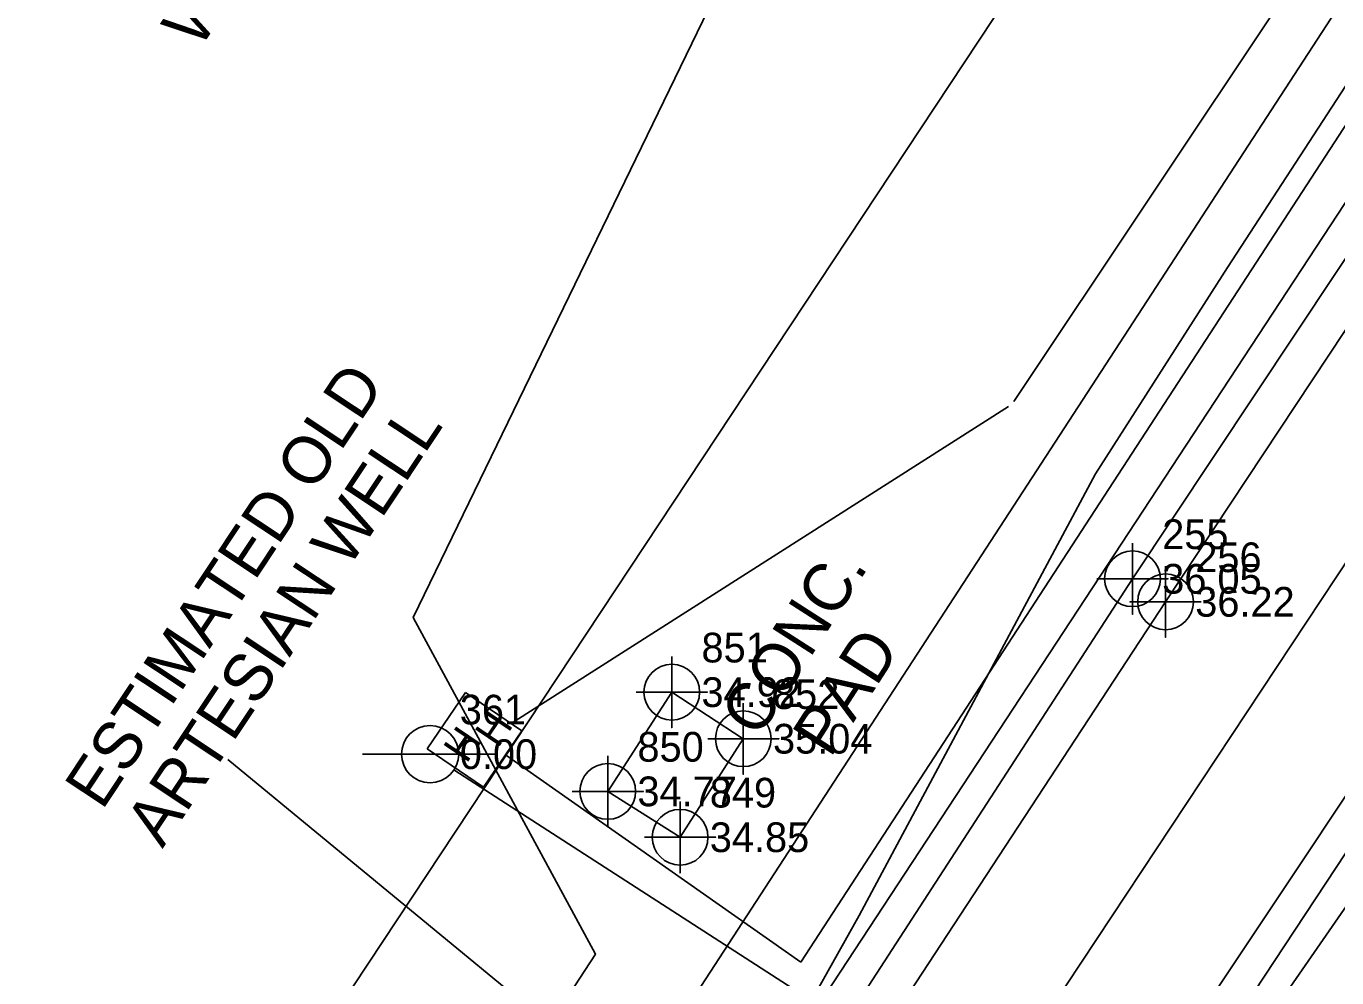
# Model space of a CAD drawing. Extents: x 2603627 to 2605187, y 896619 to 899063.
# Drawn here: x 2604513.4 to 2604623.6, y 898247.7 to 898327.7 of the extents above; entities that cross this region are included whole.
import ezdxf

# ---------------------------------------------------------------- set-up
doc = ezdxf.new("R2010")
doc.units = 0
for name, color, linetype in [('Exist Guardrail', 7, 'Continuous'), ('Exist Horizontal Alignment', 7, 'Continuous'), ('Exist Other Culture Area Outline Leader', 7, 'Continuous'), ('Exist Other Culture Area Outline Text', 7, 'Continuous'), ('Exist Right of Way Line', 7, 'Continuous'), ('Exist Roads EOP', 7, 'Continuous'), ('Exist Roads EOP Cogo Elevation', 7, 'Continuous'), ('Exist Roads EOP Cogo Number', 7, 'Continuous'), ('Exist Roads EOP Cogo Point CELL', 7, 'Continuous'), ('Exist Roads EOP Other', 7, 'Continuous'), ('Exist Roads EOP Other Cogo Elevation', 7, 'Continuous'), ('Exist Roads EOP Other Cogo Number', 7, 'Continuous'), ('Exist Roads EOP Other Cogo Point CELL', 7, 'Continuous'), ('Exist Roads EOP Other Text', 7, 'Continuous'), ('Exist Roads EOT', 7, 'Continuous'), ('Exist Roads EOT Cogo Elevation', 7, 'Continuous'), ('Exist Roads EOT Cogo Number', 7, 'Continuous'), ('Exist Roads EOT Cogo Point CELL', 7, 'Continuous'), ('Exist Utilities Telephone Hand Hole CELL', 7, 'Continuous'), ('Exist Utilities Telephone Pole CELL', 7, 'Continuous'), ('Exist Utilities Telephone Pole Cogo Elevation', 7, 'Continuous'), ('Exist Utilities Telephone Pole Cogo Number', 7, 'Continuous'), ('Exist Utilities Telephone UG Cable SUE LOS C', 7, 'Continuous'), ('Exist Utilities Telephone UG FO SUE LOS C', 7, 'Continuous'), ('Exist Vegetation Woods Line', 7, 'Continuous'), ('Exist Vegetation Woods Line Text', 7, 'Continuous')]:
    doc.layers.add(name, color=color, linetype=linetype)

# ---------------------------------------------------------------- blocks, each defined once
blk = doc.blocks.new('EXIST ROADS EOP COGO POINT')
at = {"layer": 'Exist Roads EOP Cogo Point CELL'}
blk.add_lwpolyline([(0, 0.06), (0, -0.06), (0, 0), (0.06, 0), (-0.06, 0)], dxfattribs=at)
blk.add_circle((0, 0), 0.0469, dxfattribs=at)
blk = doc.blocks.new('EXIST ROADS EOT COGO POINT')
at = {"layer": 'Exist Roads EOT Cogo Point CELL'}
blk.add_lwpolyline([(0, 0.06), (0, -0.06), (0, 0), (-0.06, 0), (0.06, 0)], dxfattribs=at)
blk.add_circle((0, 0), 0.0469, dxfattribs=at)
blk = doc.blocks.new('EXIST ROADS EOP OTHER COGO POINT')
at = {"layer": 'Exist Roads EOP Other Cogo Point CELL'}
blk.add_lwpolyline([(0, 0.06), (0, -0.06), (0, 0), (0.06, 0), (-0.06, 0)], dxfattribs=at)
blk.add_circle((0, 0), 0.0469, dxfattribs=at)

msp = doc.modelspace()

# ---------------------------------------------------------------- linework, layer by layer
at = {"layer": 'Exist Guardrail'}
for points in [[(2604549.45, 898197), (2604551.69, 898200.42), (2604561.03, 898214.38), (2604574.05, 898236.14), (2604583.44, 898252.9), (2604603.34, 898290.06), (2604614.45, 898307.44), (2604661.78, 898380.22)], [(2604631.98, 898264.56), (2604605.99, 898227.06), (2604595.34, 898211.26), (2604574.88, 898180.21)]]:
    msp.add_lwpolyline(points, dxfattribs=at)
at = {"layer": 'Exist Horizontal Alignment'}
msp.add_line((2604537.35, 898151.01), (2604647.76, 898317.92), dxfattribs=at)
at = {"layer": 'Exist Other Culture Area Outline Leader'}
msp.add_line((2604563.19, 898238.98), (2604530.32, 898266.04), dxfattribs=at)
at = {"layer": 'Exist Right of Way Line'}
msp.add_line((2604495.65, 898178.6), (2604606.06, 898345.5), dxfattribs=at)
at = {"layer": 'Exist Roads EOP'}
msp.add_line((2604600.14, 898221.38), (2604629.44, 898265.84), dxfattribs=at)
msp.add_lwpolyline([(2604577.96, 898237.27), (2604606.45, 898281.24), (2604633.89, 898322.5), (2604662.45, 898365.47), (2604690.62, 898408.06), (2604717.29, 898448.09), (2604745.46, 898490.11), (2604773.6, 898532.6), (2604800.88, 898573.95), (2604828.34, 898615.46), (2604855.1, 898656.15), (2604883.53, 898699.09), (2604911.29, 898740.95), (2604939.38, 898783.41), (2604966.33, 898824.04), (2604993.38, 898865.27), (2605022.2, 898908.38), (2605029.46, 898919.46)], dxfattribs=at)
at = {"layer": 'Exist Roads EOP Other'}
msp.add_lwpolyline([(2604568.38, 898259.49), (2604562.29, 898263.35), (2604567.68, 898271.7), (2604573.7, 898267.78), (2604568.38, 898259.49)], dxfattribs=at)
at = {"layer": 'Exist Roads EOT'}
for points in [[(2604580.65, 898235.67), (2604609.23, 898279.3), (2604636.66, 898320.72), (2604665.18, 898363.91), (2604693.37, 898406.36), (2604719.95, 898446.05), (2604748, 898488.34), (2604776.15, 898530.84), (2604803.5, 898572.3), (2604830.95, 898613.91), (2604857.58, 898654.47), (2604886.02, 898697.38), (2604913.86, 898739.33), (2604942.03, 898781.72), (2604969.06, 898822.38), (2604996.07, 898863.44), (2605024.73, 898906.73), (2605032, 898917.78)], [(2604598.04, 898223.4), (2604627.23, 898267.23), (2604654.64, 898308.57), (2604683.28, 898352.01), (2604711.27, 898394.14), (2604737.98, 898434.05), (2604766.04, 898475.94), (2604794.96, 898519.26), (2604821.61, 898559.82), (2604848.89, 898601.4), (2604876.12, 898642.73), (2604904.4, 898685.35), (2604932.33, 898727.23), (2604960.29, 898769.49), (2604987.32, 898810.19), (2605014.12, 898850.95), (2605043.08, 898894.89), (2605050.2, 898905.72)]]:
    msp.add_lwpolyline(points, dxfattribs=at)
at = {"layer": 'Exist Utilities Telephone Hand Hole CELL'}
for p, q in [((2604550.31, 898271.66), (2604547.1, 898266.92)), ((2604555.05, 898268.45), (2604550.31, 898271.66)), ((2604551.07, 898267.68), (2604551.07, 898267.68)), ((2604551.84, 898263.71), (2604555.05, 898268.45)), ((2604547.1, 898266.92), (2604551.84, 898263.71))]:
    msp.add_line(p, q, dxfattribs=at)
at = {"layer": 'Exist Utilities Telephone Pole CELL'}
for p, q in [((2604541.66, 898266.48), (2604553, 898266.48)), ((2604547.34, 898266.48), (2604547.34, 898266.48))]:
    msp.add_line(p, q, dxfattribs=at)
msp.add_circle((2604547.34, 898266.48), 2.41, dxfattribs=at)
at = {"layer": 'Exist Utilities Telephone UG Cable SUE LOS C'}
for p, q in [((2604580.04, 898245.37), (2604795.48, 898573.63)), ((2604596.46, 898296.17), (2604658.71, 898389.49)), ((2604554.16, 898269.05), (2604596.02, 898295.74)), ((2604549.35, 898265.16), (2604580.04, 898245.37))]:
    msp.add_line(p, q, dxfattribs=at)
at = {"layer": 'Exist Utilities Telephone UG FO SUE LOS C'}
for p, q in [((2604555.47, 898224.4), (2604671.2, 898402.26)), ((2604578.55, 898248.99), (2604676.14, 898398.98)), ((2604553.68, 898266.42), (2604578.55, 898248.99))]:
    msp.add_line(p, q, dxfattribs=at)
at = {"layer": 'Exist Vegetation Woods Line'}
msp.add_lwpolyline([(2604591.9, 898412.36), (2604622.51, 898404.04), (2604578.27, 898344.62), (2604545.93, 898277.97), (2604561.25, 898249.64), (2604543.06, 898221.77), (2604504.96, 898238.63), (2604486.58, 898253.52)], dxfattribs=at)

# ---------------------------------------------------------------- block references
at = {"layer": 'Exist Roads EOP Cogo Point CELL', "xscale": 50, "yscale": 50}
msp.add_blockref('EXIST ROADS EOP COGO POINT', (2604606.45, 898281.24), dxfattribs=at)
at = {"layer": 'Exist Roads EOP Other Cogo Point CELL', "xscale": 50, "yscale": 50}
for p in [(2604567.68, 898271.7), (2604573.7, 898267.78), (2604562.29, 898263.35), (2604568.38, 898259.49)]:
    msp.add_blockref('EXIST ROADS EOP OTHER COGO POINT', p, dxfattribs=at)
at = {"layer": 'Exist Roads EOT Cogo Point CELL', "xscale": 50, "yscale": 50}
msp.add_blockref('EXIST ROADS EOT COGO POINT', (2604609.23, 898279.3), dxfattribs=at)

# ---------------------------------------------------------------- texts
at = {"layer": 'Exist Other Culture Area Outline Text'}
for s, p in [('ESTIMATED OLD ', (2604519.74, 898261.68)), ('ARTESIAN WELL', (2604524.82, 898258.49))]:
    msp.add_text(s, height=4, rotation=56.4094, dxfattribs=at).set_placement(p)
at = {"layer": 'Exist Roads EOP Cogo Elevation'}
msp.add_text('36.05', height=2.5, dxfattribs=at).set_placement((2604608.95, 898279.99))
at = {"layer": 'Exist Roads EOP Cogo Number'}
msp.add_text('255', height=2.5, dxfattribs=at).set_placement((2604608.95, 898283.74))
at = {"layer": 'Exist Roads EOP Other Cogo Elevation'}
for s, p in [('34.92', (2604570.18, 898270.45)), ('35.04', (2604576.2, 898266.53)), ('34.77', (2604564.79, 898262.1)), ('34.85', (2604570.88, 898258.24))]:
    msp.add_text(s, height=2.5, dxfattribs=at).set_placement(p)
at = {"layer": 'Exist Roads EOP Other Cogo Number'}
for s, p in [('851', (2604570.18, 898274.2)), ('852', (2604576.2, 898270.28)), ('850', (2604564.79, 898265.85)), ('849', (2604570.88, 898261.99))]:
    msp.add_text(s, height=2.5, dxfattribs=at).set_placement(p)
at = {"layer": 'Exist Roads EOP Other Text'}
for s, p in [('CONC.', (2604574.96, 898267.74)), ('PAD', (2604581.02, 898266.08))]:
    msp.add_text(s, height=4, rotation=57.3037, dxfattribs=at).set_placement(p)
at = {"layer": 'Exist Roads EOT Cogo Elevation'}
msp.add_text('36.22', height=2.5, dxfattribs=at).set_placement((2604611.73, 898278.05))
at = {"layer": 'Exist Roads EOT Cogo Number'}
msp.add_text('256', height=2.5, dxfattribs=at).set_placement((2604611.73, 898281.8))
at = {"layer": 'Exist Utilities Telephone Hand Hole CELL'}
for p in [(2604553.05, 898266.93), (2604550.4, 898265.63)]:
    msp.add_text('H', height=2.5, rotation=55.8889, dxfattribs=at).set_placement(p)
at = {"layer": 'Exist Utilities Telephone Pole Cogo Elevation'}
msp.add_text('0.00', height=2.5, dxfattribs=at).set_placement((2604549.84, 898265.23))
at = {"layer": 'Exist Utilities Telephone Pole Cogo Number'}
msp.add_text('361', height=2.5, dxfattribs=at).set_placement((2604549.84, 898268.98))
at = {"layer": 'Exist Vegetation Woods Line Text'}
msp.add_text('WOODS', height=4, rotation=56.4786, dxfattribs=at).set_placement((2604527.92, 898325.7))

doc.saveas('drawing.dxf')
